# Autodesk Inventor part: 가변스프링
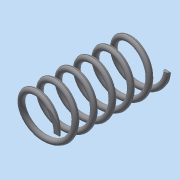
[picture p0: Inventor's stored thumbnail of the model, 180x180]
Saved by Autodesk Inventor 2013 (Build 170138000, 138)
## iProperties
Created: 2018-06
Part Number: 가변스프링
Material: 강철, 탄소
Document SubType Name: Modeling
Designer: dgall
Density: 7.87 g/cm^3
Author: dgall
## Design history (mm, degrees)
sketch "스케치1"
  geometry: L1 (0, 0)-(0, 38); L2 (0, 38)-(8, 38); L3 (0, 0)-(8, 0); C1 r 1 at (8, 0)
  constraints: 6 end point, 1 centre point, 1 coincident, 1 parallel, 1 perpendicular, 1 vertical, 1 vertical alignment
  dimensions: "d0" = 38 distance of L1.start L1.end (derived); "d1" = 16 diameter of L2.end L1; "d2" = 2 diameter of C1
feature "코일1" sketch "스케치1" pitch "d3" = 10; turns "d5" = 6; dims "d4" = 38 (= d0), "d6" = 0, angle "d7" = 90 deg, angle "d8" = 90 deg, "d9" = 0, "d10" = 0
feature "분할1"
node "작업 평면1"
feature "분할2"
node "솔리드1"
other parameters: "d11" = 0
